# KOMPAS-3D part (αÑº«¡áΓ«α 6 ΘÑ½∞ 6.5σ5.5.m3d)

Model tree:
1. Эскиз:1
2. Операция выдавливания:36
     Толщина стенки 1 = 2; Толщина стенки 2 = 6; Расстояние 1 = 1; Расстояние 2 = 3
3. Эскиз:38
4. Операция выдавливания:40
     Толщина стенки 1 = 2; Толщина стенки 2 = 6; Расстояние 1 = 5; Расстояние 2 = 3
5. Эскиз:39
6. Операция выдавливания:41
     Толщина стенки 1 = 2; Толщина стенки 2 = 6; Расстояние 1 = 1; Расстояние 2 = 3
7. Эскиз:40
8. Операция выдавливания:42
     Толщина стенки 1 = 2; Толщина стенки 2 = 2.5; Расстояние 1 = 50; Расстояние 2 = 3
9. Эскиз:41
10. Вырезать элемент выдавливания:4
     Толщина стенки 2 = 1.5; Расстояние 1 = 40
11. Эскиз:42
12. Операция выдавливания:43
     Толщина стенки 1 = 2; Толщина стенки 2 = 2.5; Расстояние 1 = 50; Расстояние 2 = 3
13. Эскиз:43
14. Вырезать элемент выдавливания:5
     Толщина стенки 2 = 1.5; Расстояние 1 = 40
15. Эскиз:44
16. Операция выдавливания:44
     Толщина стенки 1 = 2; Толщина стенки 2 = 2.5; Расстояние 1 = 10; Расстояние 2 = 3
17. Эскиз:45
18. Эскиз:46
19. Операция выдавливания:47
     Толщина стенки 1 = 2; Толщина стенки 2 = 6; Расстояние 1 = 1; Расстояние 2 = 3
20. Эскиз:47
21. Операция выдавливания:48
     Толщина стенки 1 = 2; Толщина стенки 2 = 6; Расстояние 1 = 5; Расстояние 2 = 3
22. Эскиз:48
23. Операция выдавливания:49
     Толщина стенки 1 = 2; Толщина стенки 2 = 6; Расстояние 1 = 1; Расстояние 2 = 3
24. Эскиз:49
25. Вырезать элемент выдавливания:6
     Толщина стенки 2 = 1.5; Расстояние 1 = 22
26. Эскиз:50
27. Вырезать элемент выдавливания:7
     Толщина стенки 2 = 1.5; Расстояние 1 = 1
28. Эскиз:51
29. Вырезать элемент выдавливания:8
     Толщина стенки 2 = 1.5; Расстояние 1 = 151
30. Эскиз:53
31. Операция выдавливания:51
     Толщина стенки 1 = 7; Расстояние 1 = 10; Расстояние 2 = 0.4
32. Эскиз:54
33. Вырезать элемент выдавливания:9
     Расстояние 1 = 70
34. Эскиз:55
35. Вырезать элемент выдавливания:10
     Расстояние 1 = 70; Угол 1 = 30
